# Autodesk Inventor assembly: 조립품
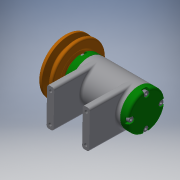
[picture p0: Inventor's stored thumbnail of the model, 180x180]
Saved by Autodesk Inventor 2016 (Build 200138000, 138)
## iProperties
Created: 2020-07
Part Number: 조립품
Material: 일반
Document SubType Name: Assembly
Designer: user
Author: user
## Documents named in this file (13)
- C:\Users\user\Desktop\700706V1025\조립품.iam
- C:\Users\user\Desktop\700706V1025\본체.ipt
- C:\Users\user\Desktop\700706V1025\베어링 6002.ipt
- C:\Users\user\Desktop\700706V1025\뒤커버.ipt
- C:\Users\user\Desktop\700706V1025\앞커버.ipt
- C:\Users\user\Desktop\700706V1025\축.ipt
- C:\Users\user\Desktop\700706V1025\오일 실 15 25 7.ipt
- C:\Users\user\Desktop\700706V1025\키 3x3x12.ipt
- C:\Users\user\Desktop\700706V1025\V벨트풀리.ipt
- C:\Users\user\Desktop\700706V1025\와셔 8x17.ipt
- C:\Users\user\Desktop\700706V1025\스프링와셔 8.ipt
- C:\Users\user\Desktop\700706V1025\너트 M8.ipt
- C:\Users\user\Desktop\700706V1025\볼트 M4x12.ipt
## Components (1 placed, 1 different names)
1. V벨트풀리:2
